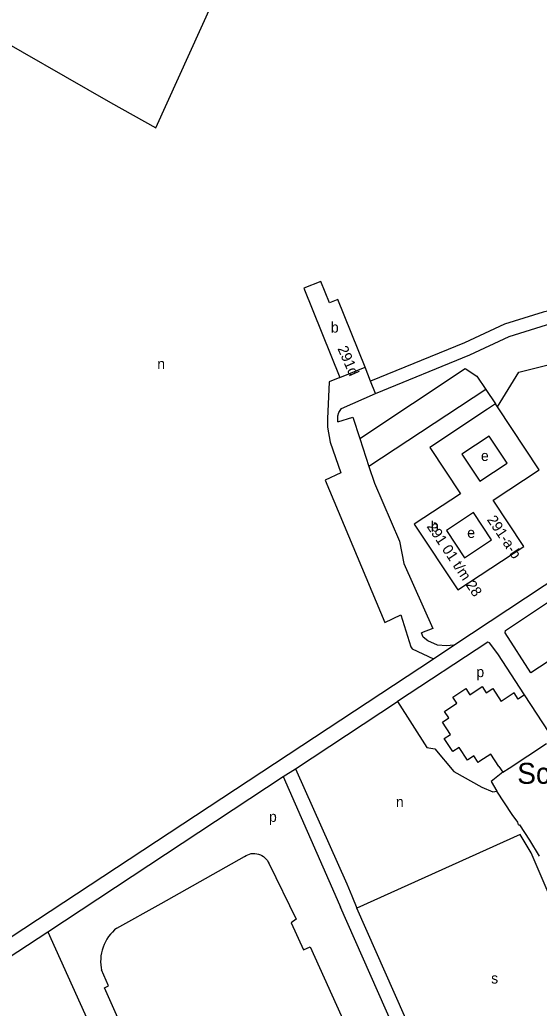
# Model space of a CAD drawing. Extents: x 161093 to 163177, y 379000 to 380904.
# Drawn here: x 161621 to 161819, y 379771.7 to 380148.5 of the extents above; entities that cross this region are included whole.
import ezdxf

# ---------------------------------------------------------------- set-up
doc = ezdxf.new("R2010")
doc.units = 0
for name, color, linetype in [('BLT_Basislijn', 7, 'Continuous'), ('BLT_Bebouwing', 7, 'Continuous'), ('BLT_Bebouwing_beschrifting', 7, 'Continuous'), ('BLT_Centroide', 7, 'Continuous'), ('BLT_Huisnummer', 7, 'Continuous'), ('BLT_Huisnummer_reeks', 7, 'Continuous')]:
    doc.layers.add(name, color=color, linetype=linetype)

msp = doc.modelspace()

# ---------------------------------------------------------------- linework, layer by layer
at = {"layer": 'BLT_Basislijn'}
for p, q in [((161754.73, 380010.69), (161752.59, 380016.06)), ((161756.59, 380006.05), (161754.73, 380010.69)), ((161798.6, 380007.52), (161754.07, 379978.24)), ((161798.6, 380007.52), (161802.29, 380002.06)), ((161750.56, 379988.89), (161754.07, 379978.24)), ((161786.38, 379910.11), (161829.93, 379938.9)), ((161778.66, 379904.88), (161786.38, 379910.11)), ((161557.29, 379759.15), (161778.66, 379904.88)), ((161726.12, 379862.97), (161764.91, 379888.57)), ((161721.45, 379859.96), (161726.12, 379862.97)), ((161726.12, 379862.97), (161745.63, 379819.08)), ((161631.7, 379800.84), (161721.45, 379859.96)), ((161721.45, 379859.96), (161741.09, 379815.14)), ((161808.67, 379845.54), (161802.76, 379854.38)), ((161745.63, 379819.08), (161747.57, 379814.49)), ((161741.09, 379815.14), (161743.21, 379810.26)), ((161747.57, 379814.49), (161749.52, 379809.87)), ((161555.8, 379751.1), (161631.7, 379800.84)), ((161631.7, 379800.84), (161686.42, 379679.79))]:
    msp.add_line(p, q, dxfattribs=at)
for points in [[(161604.59, 380146.24), (161655.66, 380116.98), (161672.91, 380107.27), (161694.48, 380155.01), (161703.07, 380174.01), (161701.22, 380174.31)], [(161882.74, 380057.59), (161871.68, 380056.08), (161865.58, 380053.91), (161856.81, 380048.84), (161846.96, 380044.35), (161834.99, 380040.35), (161820.48, 380037.07), (161805.7, 380032.48), (161790.47, 380025.37), (161754.73, 380010.69)], [(161756.59, 380006.05), (161792.48, 380020.79), (161807.5, 380027.8), (161821.77, 380032.23), (161836.34, 380035.53), (161848.8, 380039.69), (161859.11, 380044.39), (161867.69, 380049.36), (161872.87, 380051.19), (161884.19, 380052.74)], [(161803.06, 380000.9), (161811.16, 380014.13), (161853.88, 380024.91), (161874.44, 380023.71), (161890.44, 380032.52)], [(161750.56, 379988.89), (161790.7, 380015.54), (161795.16, 380012.62), (161798.6, 380007.52)], [(161742.95, 380012.17), (161738.91, 380010.5), (161738.35, 379996.41), (161738.24, 379993.24), (161739.29, 379987.53), (161743.4, 379975.84), (161737.37, 379972.96), (161760.19, 379918.76), (161766.2, 379921.62), (161769.98, 379909.4), (161770.52, 379908.66), (161778.66, 379904.88)], [(161742.22, 379995.22), (161742.25, 379997.47), (161742.56, 379998.81), (161743.64, 380000.37), (161756.59, 380006.05)], [(161742.22, 379995.22), (161747.89, 379996.96), (161750.56, 379988.89)], [(161754.07, 379978.24), (161756.17, 379971.88), (161765.68, 379949.74), (161767.43, 379941.18), (161778.37, 379916.49), (161774.12, 379914.77)], [(161822.32, 379903.85), (161815.73, 379899.53), (161805.99, 379914.75), (161806.1, 379915.69), (161853.73, 379947.46), (161854.3, 379947.43), (161863.27, 379943.3), (161868.31, 379929.21), (161877.73, 379895.05)], [(161786.38, 379910.11), (161783.67, 379909.85), (161780.23, 379910.04), (161776.52, 379911.68), (161774.76, 379913.19), (161774.12, 379914.77)], [(161813.3, 379891.12), (161803.24, 379906.81), (161800.04, 379910.92), (161799.34, 379911.29), (161764.91, 379888.57)], [(161764.91, 379888.57), (161776.09, 379871.12), (161779.22, 379870.58), (161786.4, 379861.97), (161797.15, 379856.01), (161801.25, 379854.21), (161802.76, 379854.38)], [(161805.05, 379861.61), (161800.68, 379858.06), (161802.76, 379854.38)], [(161811.12, 379841.62), (161810.76, 379842.56), (161808.67, 379845.54)], [(161811.12, 379841.62), (161811.48, 379841.53), (161815.3, 379835.79), (161818.97, 379829.7)], [(161818.6, 379824.68), (161815.87, 379830.9), (161811.73, 379837.85), (161749.52, 379809.87)], [(161706.7, 379829.52), (161707.29, 379829.9), (161707.92, 379830.21), (161708.58, 379830.44), (161709.26, 379830.6), (161709.96, 379830.68), (161710.66, 379830.68), (161711.36, 379830.59), (161712.04, 379830.43), (161712.7, 379830.2), (161713.33, 379829.89), (161713.92, 379829.51), (161714.46, 379829.06), (161714.94, 379828.56), (161715.37, 379828), (161715.73, 379827.4), (161716.02, 379826.76)], [(161674.94, 379811.56), (161706.7, 379829.52)], [(161716.02, 379826.76), (161726.38, 379805.69), (161724.49, 379804.29), (161729.14, 379793.95), (161731.73, 379795.11), (161758.83, 379734.88)], [(161848.26, 379755.5), (161830.87, 379796.01), (161818.6, 379824.68)], [(161658.02, 379802.24), (161674.94, 379811.56)], [(161686.42, 379679.79), (161782.48, 379719.76), (161777.79, 379732.06), (161743.21, 379810.26)], [(161785.66, 379728.39), (161784.58, 379730.09), (161767.66, 379768.76), (161749.52, 379809.87)], [(161658.02, 379802.24), (161657.15, 379801.5), (161656.34, 379800.71), (161655.58, 379799.86), (161654.89, 379798.96), (161654.26, 379798.01), (161653.69, 379797.02), (161653.2, 379795.99), (161652.78, 379794.93), (161652.44, 379793.85), (161652.17, 379792.74), (161651.98, 379791.62), (161651.88, 379790.48), (161651.85, 379789.35), (161651.9, 379788.21), (161652.03, 379787.08), (161652.16, 379786.35)], [(161690.13, 379706.56), (161671.49, 379746.97), (161667.17, 379748.31), (161653.31, 379779.49), (161654.88, 379780.21), (161652.16, 379786.35)]]:
    msp.add_lwpolyline(points, dxfattribs=at)
at = {"layer": 'BLT_Bebouwing'}
for p, q in [((161742.95, 380012.17), (161752.59, 380016.06)), ((161802.29, 380002.06), (161799.21, 380000.01)), ((161803.06, 380000.9), (161802.29, 380002.06)), ((161822.78, 379876.76), (161813.3, 379891.12)), ((161807.5, 379863.23), (161821.74, 379872.61)), ((161803.56, 379863.86), (161800.46, 379868.58)), ((161803.56, 379863.86), (161805.05, 379861.61)), ((161805.05, 379861.61), (161807.5, 379863.23))]:
    msp.add_line(p, q, dxfattribs=at)
for points in [[(161752.59, 380016.06), (161742.18, 380041.83), (161739.03, 380040.55), (161735.7, 380048.8), (161729.21, 380046.18), (161742.95, 380012.17)], [(161799.21, 380000.01), (161777.24, 379985.42), (161788.95, 379967.8), (161771.33, 379956.22), (161788, 379931.13), (161813.05, 379947.76), (161801.37, 379965.34), (161818.93, 379976.99), (161803.06, 380000.9)], [(161800.46, 379868.58), (161796.29, 379865.82), (161795.65, 379865.4), (161794, 379867.89), (161791.59, 379866.29), (161788.43, 379871.06), (161786.06, 379869.49), (161785.52, 379870.3), (161782.76, 379874.47), (161785.14, 379876.04), (161782.04, 379880.72), (161784.47, 379882.33), (161782.81, 379884.83), (161787.57, 379887.99), (161786.07, 379890.25), (161791.01, 379893.52), (161792.54, 379891.21), (161797.2, 379894.29), (161798.8, 379891.88), (161801.27, 379893.52), (161804.44, 379888.61)], [(161813.3, 379891.12), (161810.91, 379889.54), (161809.36, 379891.87), (161804.44, 379888.61)]]:
    msp.add_lwpolyline(points, dxfattribs=at)
for points in [[(161799.82, 379989.81), (161789.47, 379982.95), (161796.33, 379972.65), (161806.69, 379979.45)], [(161793.92, 379960.61), (161783.6, 379953.75), (161790.46, 379943.41), (161800.79, 379950.27)]]:
    msp.add_lwpolyline(points, close=True, dxfattribs=at)

# ---------------------------------------------------------------- texts
at = {"layer": 'BLT_Bebouwing_beschrifting'}
msp.add_text('School', height=8, dxfattribs=at).set_placement((161810.57, 379857.23))
at = {"layer": 'BLT_Centroide'}
for s, p in [('b', (161739.57, 380029.28)), ('n', (161673.42, 380015.35)), ('e', (161796.75, 379980.31)), ('b', (161777.66, 379953.38)), ('e', (161791.51, 379950.98)), ('p', (161795, 379897.9)), ('n', (161764.34, 379848.33)), ('p', (161715.99, 379842.71)), ('s', (161800.63, 379781.09))]:
    msp.add_text(s, height=4, dxfattribs=at).set_placement(p)
at = {"layer": 'BLT_Huisnummer'}
msp.add_text('291d', height=4, rotation=293.7691, dxfattribs=at).set_placement((161742.02, 380023.18))
at = {"layer": 'BLT_Huisnummer_reeks'}
for s, p in [('291-a-b', (161798.9, 379957.93)), ('291 01 t/m 28', (161775.94, 379955.34))]:
    msp.add_text(s, height=4, rotation=303.7691, dxfattribs=at).set_placement(p)

doc.saveas('drawing.dxf')
